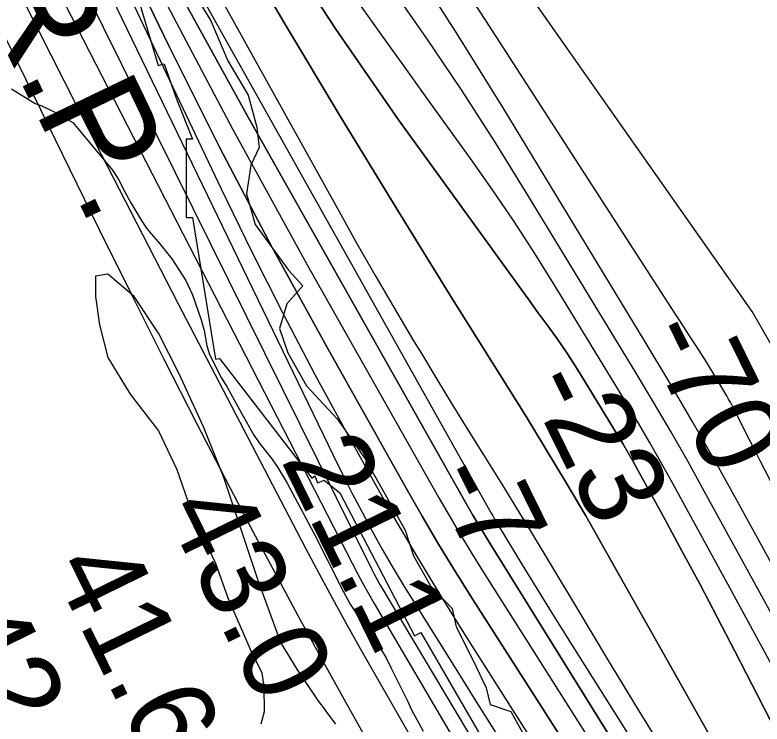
# Model space of a CAD drawing. Extents: x 3177185 to 3215018, y 812988 to 838321.
# Drawn here: x 3197779 to 3198368, y 818609 to 819169 of the extents above; entities that cross this region are included whole.
import ezdxf

# ---------------------------------------------------------------- set-up
doc = ezdxf.new("R2010")
doc.units = 0
for name, color, linetype in [('V-RIVR-EDGE', 7, 'Continuous'), ('V-RIVR-RANG', 7, 'Continuous'), ('V-RRAP-RVMT', 7, 'Continuous'), ('V-SITE-VEGE', 7, 'Continuous'), ('V-TOPO-DPTH', 7, 'Continuous'), ('V-TOPO-MAJR', 7, 'Continuous'), ('V-TOPO-MINR', 7, 'Continuous'), ('V-TOPO-WATR', 7, 'Continuous'), ('V-TOPO-WATR-IDEN', 7, 'Continuous')]:
    doc.layers.add(name, color=color, linetype=linetype)

msp = doc.modelspace()

# ---------------------------------------------------------------- linework, layer by layer
at = {"layer": 'V-RIVR-EDGE'}
msp.add_lwpolyline([(3197912.54, 819198.75), (3197933.32, 819164.79), (3197946.71, 819133.03), (3197962.73, 819106.04), (3197969.62, 819080.81), (3197971.32, 819064.72), (3197964.77, 819050.83), (3197961.23, 819028.23), (3197968.13, 819003.87), (3197994.55, 818967.73), (3198005.83, 818955.53), (3197993.18, 818941.22), (3197987.49, 818921.67), (3197993.96, 818902.53), (3198008.67, 818876.41), (3198032.95, 818850.27), (3198055.04, 818818.92), (3198086.63, 818762.33), (3198093.1, 818742.32), (3198106.52, 818718.38), (3198123.86, 818700.52), (3198126.87, 818686.16), (3198140.28, 818659.62), (3198150.66, 818637.86), (3198153.67, 818624.81), (3198170.17, 818619.12), (3198180.56, 818600.4)], dxfattribs=at)
at = {"layer": 'V-RRAP-RVMT'}
for p, q in [((3197870.22, 819201.1), (3197891.56, 819129.43)), ((3197891.56, 819129.43), (3197896.26, 819130.87)), ((3197896.26, 819130.87), (3197905.92, 819103.64)), ((3197905.92, 819103.64), (3197918.76, 819071.23)), ((3197918.76, 819071.23), (3197913.62, 819071.19)), ((3197913.62, 819071.19), (3197913.76, 819009.42)), ((3197913.76, 819009.42), (3197918.82, 819009.48)), ((3197918.82, 819009.48), (3197936.87, 818897.63)), ((3197936.87, 818897.63), (3197940.03, 818898.13)), ((3197940.03, 818898.13), (3198012.97, 818803.65)), ((3198012.97, 818803.65), (3198015.31, 818805.48)), ((3198015.31, 818805.48), (3198017.5, 818799.94)), ((3198017.5, 818799.94), (3198022.68, 818801.93)), ((3198022.68, 818801.93), (3198034.97, 818791.82)), ((3198034.97, 818791.82), (3198094.12, 818679.04)), ((3198094.12, 818679.04), (3198099.02, 818681.55)), ((3198099.02, 818681.55), (3198171.97, 818555.99))]:
    msp.add_line(p, q, dxfattribs=at)
at = {"layer": 'V-SITE-VEGE'}
for p, q in [((3197775.79, 819111.1), (3197794.5, 819099.55)), ((3197794.5, 819099.55), (3197799.77, 819097.58)), ((3197799.77, 819097.58), (3197809.52, 819092.82)), ((3197809.52, 819092.82), (3197824.15, 819084.47)), ((3197824.15, 819084.47), (3197855.63, 819046.77)), ((3197855.63, 819046.77), (3197860.14, 819039.94)), ((3197860.14, 819039.94), (3197865.09, 819030.28)), ((3197865.09, 819030.28), (3197870.03, 819021.03)), ((3197870.03, 819021.03), (3197878.65, 819006.56)), ((3197878.65, 819006.56), (3197882.34, 819000.94)), ((3197882.34, 819000.94), (3197886.43, 818996.12)), ((3197886.43, 818996.12), (3197892.97, 818988.5)), ((3197892.97, 818988.5), (3197902.38, 818976.87)), ((3197902.38, 818976.87), (3197913.46, 818959.59)), ((3197851.8, 818964.78), (3197842.16, 818963.18)), ((3197842.16, 818963.18), (3197842.16, 818947.09)), ((3197872.7, 818947.09), (3197851.8, 818964.78)), ((3197913.46, 818959.59), (3197918.82, 818948.32)), ((3197842.16, 818947.09), (3197845.37, 818924.57)), ((3197891.99, 818918.14), (3197872.7, 818947.09)), ((3197918.82, 818948.32), (3197925.48, 818928.58)), ((3197925.48, 818928.58), (3197927.98, 818920.11)), ((3197845.37, 818924.57), (3197851.8, 818898.84)), ((3197927.98, 818920.11), (3197930.12, 818908)), ((3197908.06, 818885.97), (3197891.99, 818918.14)), ((3197930.12, 818908), (3197932.2, 818901.15)), ((3197851.8, 818898.84), (3197869.48, 818869.89)), ((3197932.2, 818901.15), (3197933.44, 818898.74)), ((3197933.44, 818898.74), (3197936.33, 818892.7)), ((3197936.33, 818892.7), (3197941.27, 818883.05)), ((3197927.35, 818844.15), (3197908.06, 818885.97)), ((3197941.27, 818883.05), (3197946.19, 818875.41)), ((3197946.19, 818875.41), (3197957.3, 818854.9)), ((3197869.48, 818869.89), (3197891.99, 818840.93)), ((3197957.3, 818854.9), (3197967.16, 818837.61)), ((3197943.43, 818803.94), (3197927.35, 818844.15)), ((3197891.99, 818840.93), (3197906.46, 818810.37)), ((3197967.16, 818837.61), (3197972.09, 818830.38)), ((3197972.09, 818830.38), (3197980.67, 818819.95)), ((3197980.67, 818819.95), (3197985.59, 818812.72)), ((3197906.46, 818810.37), (3197919.32, 818773.38)), ((3197985.59, 818812.72), (3197993.4, 818799.45)), ((3197954.68, 818770.16), (3197943.43, 818803.94)), ((3197993.4, 818799.45), (3198014.39, 818760.03)), ((3197919.32, 818773.38), (3197937, 818736.39)), ((3197970.75, 818721.91), (3197954.68, 818770.16)), ((3198014.39, 818760.03), (3198025.51, 818738.31)), ((3198025.51, 818738.31), (3198037.87, 818713.77)), ((3197937, 818736.39), (3197946.64, 818709.04)), ((3197988.44, 818673.66), (3197970.75, 818721.91)), ((3198037.87, 818713.77), (3198043.21, 818704.11)), ((3197946.64, 818709.04), (3197964.32, 818668.6)), ((3198043.21, 818704.11), (3198051.42, 818691.66)), ((3198051.42, 818691.66), (3198054.7, 818686.84)), ((3198054.7, 818686.84), (3198060.83, 818679.21)), ((3198060.83, 818679.21), (3198064.12, 818673.99)), ((3198001.3, 818652.75), (3197988.44, 818673.66)), ((3198064.12, 818673.99), (3198071.51, 818661.53)), ((3197964.32, 818668.6), (3197973.39, 818649.69)), ((3198071.51, 818661.53), (3198075.63, 818653.48)), ((3197973.39, 818649.69), (3197975.11, 818638.79)), ((3198017.37, 818628.62), (3198001.3, 818652.75)), ((3198075.63, 818653.48), (3198088.41, 818627.73)), ((3197975.11, 818638.79), (3197975.3, 818618.98)), ((3198031.84, 818609.32), (3198017.37, 818628.62)), ((3198088.41, 818627.73), (3198091.71, 818620.49)), ((3197975.3, 818618.98), (3197972.56, 818609.25)), ((3198091.71, 818620.49), (3198097.47, 818610.03)), ((3198097.47, 818610.03), (3198100.76, 818603.59))]:
    msp.add_line(p, q, dxfattribs=at)
at = {"layer": 'V-TOPO-DPTH'}
for points in [[(3197624.2, 819659.66), (3198029.73, 818821.68), (3198037.18, 818806.56), (3198044.78, 818791.53), (3198052.61, 818776.61), (3198060.58, 818761.76), (3198068.8, 818747.05), (3198077.19, 818732.45), (3198085.85, 818718), (3198094.69, 818703.66), (3198109.68, 818679.82), (3198126.13, 818653.62), (3198142.54, 818627.4), (3198158.91, 818601.16), (3198175.24, 818574.89), (3198308.75, 818359.79), (3198362.64, 818359.67)], [(3197827.26, 819387.33), (3198034.41, 819014.08), (3198048.82, 818988.41), (3198063.42, 818962.85), (3198078.27, 818937.43), (3198093.3, 818912.12), (3198099.44, 818901.88), (3198111.58, 818881.8), (3198123.8, 818861.75), (3198136.12, 818841.78), (3198148.51, 818821.85), (3198164.32, 818796.59), (3198168.84, 818789.31), (3198173.34, 818782.01), (3198177.8, 818774.69), (3198182.23, 818767.35), (3198221.89, 818701.26), (3198246.22, 818660.91), (3198270.68, 818620.65), (3198295.32, 818580.49), (3198320.09, 818540.42), (3198432.49, 818359.5), (3198398.39, 818359.58)], [(3197827.26, 819387.33), (3198034.41, 819014.08), (3198048.82, 818988.41), (3198063.42, 818962.85), (3198078.27, 818937.43), (3198093.3, 818912.12), (3198099.44, 818901.88), (3198111.58, 818881.8), (3198123.8, 818861.75), (3198136.12, 818841.78), (3198148.51, 818821.85), (3198164.32, 818796.59), (3198168.84, 818789.31), (3198173.34, 818782.01), (3198177.8, 818774.69), (3198182.23, 818767.35), (3198221.89, 818701.26), (3198246.22, 818660.91), (3198270.68, 818620.65), (3198295.32, 818580.49), (3198320.09, 818540.42), (3198432.49, 818359.5)], [(3198432.49, 818359.5), (3198464.39, 818359.43), (3198424.8, 818427.72), (3198378.97, 818508.11), (3198244.61, 818746.78), (3198229.21, 818773.7), (3198213.56, 818800.47), (3198197.54, 818827.02), (3198181.28, 818853.43), (3198124.09, 818944.81), (3198079.41, 819017.01), (3198035.2, 819089.5), (3197991.7, 819162.41), (3197948.67, 819235.62)], [(3197948.67, 819235.62), (3197991.7, 819162.41), (3198035.2, 819089.5), (3198079.41, 819017.01), (3198124.09, 818944.81), (3198181.28, 818853.43), (3198197.54, 818827.02), (3198213.56, 818800.47), (3198229.21, 818773.7), (3198244.61, 818746.78), (3198378.97, 818508.11), (3198424.8, 818427.72), (3198464.39, 818359.43)], [(3198393.07, 818577.31), (3198346.96, 818666.85), (3198333.28, 818693.17), (3198319.47, 818719.42), (3198305.45, 818745.57), (3198291.3, 818771.65), (3198270.37, 818809.9), (3198266.54, 818816.77), (3198262.65, 818823.61), (3198258.67, 818830.4), (3198254.63, 818837.15), (3198228.35, 818880.41), (3198221.41, 818891.51), (3198214.27, 818902.48), (3198206.86, 818913.26), (3198199.25, 818923.91), (3198191.51, 818934.48), (3198183.79, 818945.05), (3198176.09, 818955.65), (3198168.4, 818966.25), (3198081.41, 819086.53), (3198031.77, 819158.23), (3197984.16, 819231.2)], [(3197984.16, 819231.2), (3198031.77, 819158.23), (3198081.41, 819086.53), (3198168.4, 818966.25), (3198176.09, 818955.65), (3198183.79, 818945.05), (3198191.51, 818934.48), (3198199.25, 818923.91), (3198206.86, 818913.26), (3198214.27, 818902.48), (3198221.41, 818891.51), (3198228.35, 818880.41), (3198254.63, 818837.15), (3198258.67, 818830.4), (3198262.65, 818823.61), (3198266.54, 818816.77), (3198270.37, 818809.9), (3198291.3, 818771.65), (3198305.45, 818745.57), (3198319.47, 818719.42), (3198333.28, 818693.17), (3198346.96, 818666.85), (3198393.07, 818577.31)], [(3198362.64, 818359.67), (3198140.09, 818707.79), (3198126.46, 818729.51), (3198113.09, 818751.37), (3198100.1, 818773.46), (3198087.35, 818795.7), (3198024.69, 818907.23), (3197981.71, 818985.8), (3197939.92, 819065), (3197899.93, 819145.11), (3197861.14, 819225.85)], [(3198362.64, 818359.67), (3198140.09, 818707.79), (3198126.46, 818729.51), (3198113.09, 818751.37), (3198100.1, 818773.46), (3198087.35, 818795.7), (3198024.69, 818907.23), (3197981.71, 818985.8), (3197939.92, 819065), (3197899.93, 819145.11), (3197861.14, 819225.85)], [(3198398.39, 818359.58), (3198369.94, 818404.72), (3198313.23, 818495.3), (3198256.7, 818585.99), (3198152.22, 818754.17), (3198148.11, 818760.89), (3198144.05, 818767.63), (3198140.08, 818774.42), (3198136.17, 818781.25), (3197962.83, 819088.03), (3197905.07, 819193.56)], [(3197905.07, 819193.56), (3197962.83, 819088.03), (3198136.17, 818781.25), (3198140.08, 818774.42), (3198144.05, 818767.63), (3198148.11, 818760.89), (3198152.22, 818754.17), (3198256.7, 818585.99), (3198313.23, 818495.3), (3198369.94, 818404.72), (3198398.39, 818359.58), (3198362.64, 818359.67)]]:
    msp.add_lwpolyline(points, dxfattribs=at)
at = {"layer": 'V-TOPO-MAJR'}
for points in [[(3197169.42, 820662.33), (3197339.43, 820193.69), (3197370.31, 820110.2), (3197401.88, 820026.96), (3197434.48, 819944.13), (3197467.77, 819861.56), (3197519.87, 819734.61), (3197527.79, 819715.79), (3197535.92, 819697.07), (3197544.37, 819678.49), (3197553.04, 819660.01), (3197671.61, 819412.71), (3197729.11, 819294.29), (3197787.4, 819176.27), (3197846.87, 819058.84), (3197907.13, 818941.8), (3198007.95, 818748.35), (3198018.49, 818728.39), (3198029.19, 818708.51), (3198040.12, 818688.76), (3198051.2, 818669.08), (3198170.24, 818460.43), (3198223.54, 818367.96), (3198228.2, 818359.98)], [(3198536.92, 818359.26), (3198468.34, 818486.32), (3198437.12, 818544.05), (3198405.82, 818601.75), (3198374.42, 818659.39), (3198342.95, 818716.99), (3198296.61, 818801.61), (3198288.15, 818816.81), (3198279.56, 818831.93), (3198270.76, 818846.94), (3198261.83, 818861.87), (3198205.14, 818955.16), (3198189.1, 818980.86), (3198172.66, 819006.29), (3198155.62, 819031.31), (3198138.17, 819056.08), (3198120.45, 819080.66), (3198102.76, 819105.26), (3198085.13, 819129.91), (3198067.53, 819154.58), (3198018.36, 819223.67)]]:
    msp.add_lwpolyline(points, dxfattribs=at)
at = {"layer": 'V-TOPO-MINR'}
for points in [[(3197277.79, 820810.78), (3197401.73, 820396.89), (3197436.71, 820284.8), (3197473.4, 820173.3), (3197512.67, 820062.68), (3197553.64, 819952.65), (3197626.76, 819763.05), (3197632.6, 819748.31), (3197638.61, 819733.65), (3197644.89, 819719.1), (3197651.35, 819704.62), (3197787.76, 819406.19), (3197839.85, 819296), (3197893.8, 819186.76), (3197950.54, 819078.95), (3198009.15, 818972.08), (3198113.19, 818788), (3198121.27, 818773.95), (3198129.5, 818759.98), (3198137.92, 818746.14), (3198146.49, 818732.38), (3198382.49, 818359.62)], [(3197172.15, 820777.18), (3197284.37, 820430.79), (3197325.56, 820308.2), (3197368.49, 820186.24), (3197414.05, 820065.24), (3197461.36, 819944.88), (3197552.51, 819720.11), (3197555.61, 819712.63), (3197558.79, 819705.19), (3197562.08, 819697.79), (3197565.45, 819690.43), (3197615.39, 819583.45), (3197644.13, 819522.79), (3197673.32, 819462.35), (3197703.2, 819402.24), (3197733.53, 819342.36), (3198044.81, 818736.38), (3198049.01, 818728.36), (3198053.3, 818720.39), (3198057.73, 818712.5), (3198062.25, 818704.66), (3198264.61, 818359.89)], [(3197637.65, 819670.64), (3197941.36, 819032.03), (3197965.34, 818982.82), (3197989.92, 818933.92), (3198015.41, 818885.48), (3198041.5, 818837.36), (3198059.96, 818804.09), (3198077.55, 818773), (3198095.51, 818742.13), (3198114, 818711.57), (3198132.86, 818681.23), (3198213.39, 818554.16), (3198272.67, 818460.38), (3198331.82, 818366.51), (3198336.08, 818359.73)], [(3197624.2, 819659.66), (3198029.73, 818821.68), (3198037.18, 818806.56), (3198044.78, 818791.53), (3198052.61, 818776.61), (3198060.58, 818761.76), (3198068.8, 818747.05), (3198077.19, 818732.45), (3198085.85, 818718), (3198094.69, 818703.66), (3198109.68, 818679.82), (3198126.13, 818653.62), (3198142.54, 818627.4), (3198158.91, 818601.16), (3198175.24, 818574.89), (3198308.75, 818359.79)], [(3197539.23, 819625.55), (3197844.87, 819000.56), (3197870.23, 818949.23), (3197895.87, 818898.04), (3197921.93, 818847.06), (3197948.26, 818796.22), (3197966.2, 818761.92), (3197983.92, 818728.42), (3198001.83, 818695.02), (3198020.05, 818661.79), (3198038.46, 818628.67), (3198052.11, 818604.36), (3198077.6, 818559.22), (3198103.24, 818514.16), (3198129.1, 818469.23), (3198155.09, 818424.38), (3198192.58, 818360.06)], [(3197692.43, 819474.04), (3198060.37, 818731.31), (3198061.88, 818728.34), (3198063.45, 818725.39), (3198065.07, 818722.48), (3198066.75, 818719.59), (3198161.12, 818561.11), (3198210.21, 818479.12), (3198259.59, 818397.31), (3198282.45, 818359.85)], [(3197827.26, 819387.33), (3198034.41, 819014.08), (3198048.82, 818988.41), (3198063.42, 818962.85), (3198078.27, 818937.43), (3198093.3, 818912.12), (3198099.44, 818901.88), (3198111.58, 818881.8), (3198123.8, 818861.75), (3198136.12, 818841.78), (3198148.51, 818821.85), (3198164.32, 818796.59), (3198168.84, 818789.31), (3198173.34, 818782.01), (3198177.8, 818774.69), (3198182.23, 818767.35), (3198221.89, 818701.26), (3198246.22, 818660.91), (3198270.68, 818620.65), (3198295.32, 818580.49), (3198320.09, 818540.42), (3198432.49, 818359.5)], [(3198645.62, 818359.01), (3198615.8, 818424.32), (3198579.71, 818502.08), (3198542.98, 818579.54), (3198505.3, 818656.53), (3198466.98, 818733.21), (3198415.12, 818835.41), (3198402.02, 818860.64), (3198388.61, 818885.7), (3198374.73, 818910.5), (3198360.54, 818935.14), (3198068.53, 819351.22)], [(3197891.8, 819244.61), (3198154.57, 818775.85), (3198155.75, 818773.78), (3198156.36, 818772.76), (3198156.97, 818771.73), (3198179.13, 818735.21), (3198190.88, 818715.96), (3198202.7, 818696.74), (3198214.61, 818677.59), (3198226.59, 818658.48), (3198414.99, 818359.54)], [(3198379.09, 818793.67), (3198367.01, 818817.32), (3198363.08, 818825.01), (3198359.16, 818832.71), (3198355.24, 818840.4), (3198351.33, 818848.1), (3198346.11, 818858.39), (3198344.79, 818860.94), (3198343.44, 818863.46), (3198342.04, 818865.96), (3198340.61, 818868.44), (3198332.77, 818881.77), (3198328.8, 818888.4), (3198324.77, 818894.98), (3198320.65, 818901.51), (3198316.46, 818908), (3198312.23, 818914.46), (3198308, 818920.93), (3198303.8, 818927.41), (3198299.6, 818933.89), (3198150.31, 819165.08), (3198099.84, 819242.43)], [(3197948.67, 819235.62), (3197991.7, 819162.41), (3198035.2, 819089.5), (3198079.41, 819017.01), (3198124.09, 818944.81), (3198181.28, 818853.43), (3198197.54, 818827.02), (3198213.56, 818800.47), (3198229.21, 818773.7), (3198244.61, 818746.78), (3198378.97, 818508.11), (3198424.8, 818427.72), (3198464.39, 818359.43)], [(3197984.16, 819231.2), (3198031.77, 819158.23), (3198081.41, 819086.53), (3198168.4, 818966.25), (3198176.09, 818955.65), (3198183.79, 818945.05), (3198191.51, 818934.48), (3198199.25, 818923.91), (3198206.86, 818913.26), (3198214.27, 818902.48), (3198221.41, 818891.51), (3198228.35, 818880.41), (3198254.63, 818837.15), (3198258.67, 818830.4), (3198262.65, 818823.61), (3198266.54, 818816.77), (3198270.37, 818809.9), (3198291.3, 818771.65), (3198305.45, 818745.57), (3198319.47, 818719.42), (3198333.28, 818693.17), (3198346.96, 818666.85), (3198393.07, 818577.31)], [(3198584.11, 818359.15), (3198580.69, 818365.14), (3198541.3, 818435.29), (3198502.32, 818505.68), (3198349.13, 818785.06), (3198331.4, 818816.9), (3198313.38, 818848.58), (3198294.94, 818880.02), (3198276.22, 818911.29), (3198164.01, 819095.95), (3198127.18, 819155.25), (3198089.58, 819214.05)], [(3197905.07, 819193.56), (3197962.83, 819088.03), (3198136.17, 818781.25), (3198140.08, 818774.42), (3198144.05, 818767.63), (3198148.11, 818760.89), (3198152.22, 818754.17), (3198256.7, 818585.99), (3198313.23, 818495.3), (3198369.94, 818404.72), (3198398.39, 818359.58)], [(3198563.37, 818359.2), (3198543.13, 818395.04), (3198493.33, 818483.83), (3198443.95, 818572.84), (3198394.83, 818662), (3198322.86, 818793.33), (3198309.77, 818816.85), (3198296.47, 818840.26), (3198282.85, 818863.48), (3198269.02, 818886.58), (3198183.61, 819027.15), (3198157.65, 819068.85), (3198131.09, 819110.16), (3198103.63, 819150.88), (3198075.59, 819191.21)]]:
    msp.add_lwpolyline(points, dxfattribs=at)
at = {"layer": 'V-TOPO-WATR'}
msp.add_lwpolyline([(3197861.14, 819225.85), (3197899.93, 819145.11), (3197939.92, 819065), (3197981.71, 818985.8), (3198024.69, 818907.23), (3198087.35, 818795.7), (3198100.1, 818773.46), (3198113.09, 818751.37), (3198126.46, 818729.51), (3198140.09, 818707.79), (3198362.64, 818359.67)], dxfattribs=at)

# ---------------------------------------------------------------- texts
at = {"layer": 'V-RIVR-RANG'}
for s, rotation, p in [('-70', 296.23692, (3198273.11, 818917.61)), ('-23', 296.23692, (3198181.21, 818877.88)), ('21.1', 296.10833, (3197988.04, 818817.99)), ('-7', 296.23692, (3198105.98, 818804.31)), ('43.0', 296.10833, (3197896.03, 818778.5)), ('41.6', 296.10833, (3197806.81, 818733.33)), ('42.8', 296.10833, (3197717.94, 818687.44))]:
    msp.add_text(s, height=67, rotation=rotation, dxfattribs=at).set_placement(p)
at = {"layer": 'V-TOPO-WATR-IDEN'}
msp.add_text('L.W.R.P.', height=83, rotation=295.7117, dxfattribs=at).set_placement((3197646.52, 819399.96))

doc.saveas('drawing.dxf')
